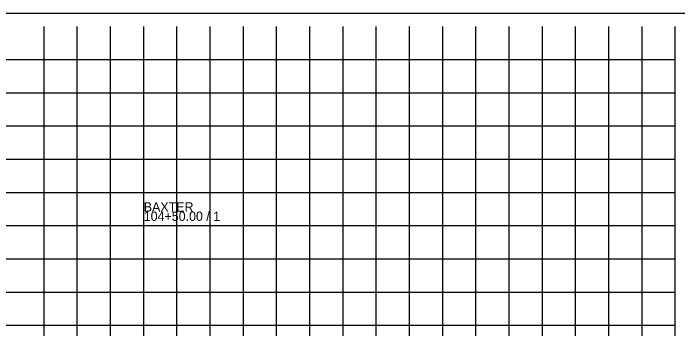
# Model space of a CAD drawing. Extents: x 5868 to 6683, y 2883 to 19120.
# Drawn here: x 6144.5 to 6344.5, y 7508 to 7603 of the extents above; entities that cross this region are included whole.
import ezdxf

# ---------------------------------------------------------------- set-up
doc = ezdxf.new("R2010")
doc.units = 0
for name, color, linetype in [('DESIGN - SCRATCH - User 1', 7, 'Continuous'), ('DESIGN - SHEET - Light Grid', 7, 'Continuous'), ('DESIGN - SHEET - Linework', 7, 'Continuous'), ('DESIGN - SHEET - Plot Shape', 7, 'Continuous')]:
    doc.layers.add(name, color=color, linetype=linetype)

msp = doc.modelspace()

# ---------------------------------------------------------------- linework, layer by layer
at = {"layer": 'DESIGN - SCRATCH - User 1'}
msp.add_line((6193.78, 7445.07), (6193.78, 7538.06), dxfattribs=at)
at = {"layer": 'DESIGN - SHEET - Light Grid'}
msp.add_line((6193.78, 7445.07), (6193.78, 7543.29), dxfattribs=at)
at = {"layer": 'DESIGN - SHEET - Linework'}
for p, q in [((6153.78, 7389.07), (6153.78, 7599.07)), ((6163.78, 7389.07), (6163.78, 7599.07)), ((6173.78, 7389.07), (6173.78, 7599.07)), ((6183.78, 7389.07), (6183.78, 7599.07)), ((6193.78, 7389.07), (6193.78, 7599.07)), ((6203.78, 7389.07), (6203.78, 7599.07)), ((6213.78, 7389.07), (6213.78, 7599.07)), ((6223.78, 7389.07), (6223.78, 7599.07)), ((6233.78, 7389.07), (6233.78, 7599.07)), ((6243.78, 7389.07), (6243.78, 7599.07)), ((6253.78, 7389.07), (6253.78, 7599.07)), ((6263.78, 7389.07), (6263.78, 7599.07)), ((6273.78, 7389.07), (6273.78, 7599.07)), ((6283.78, 7389.07), (6283.78, 7599.07)), ((6293.78, 7389.07), (6293.78, 7599.07)), ((6303.78, 7389.07), (6303.78, 7599.07)), ((6313.78, 7389.07), (6313.78, 7599.07)), ((6323.78, 7389.07), (6323.78, 7599.07)), ((6333.78, 7389.07), (6333.78, 7599.07)), ((6043.78, 7589.07), (6343.78, 7589.07)), ((6043.78, 7579.07), (6343.78, 7579.07)), ((6043.78, 7569.07), (6343.78, 7569.07)), ((6043.78, 7559.07), (6343.78, 7559.07)), ((6043.78, 7549.07), (6343.78, 7549.07)), ((6043.78, 7539.07), (6343.78, 7539.07)), ((6043.78, 7529.07), (6343.78, 7529.07)), ((6043.78, 7519.07), (6343.78, 7519.07)), ((6043.78, 7509.07), (6343.78, 7509.07))]:
    msp.add_line(p, q, dxfattribs=at)
msp.add_lwpolyline([(6043.78, 7599.07), (6043.78, 7389.07), (6343.78, 7389.07), (6343.78, 7599.07)], dxfattribs=at)
at = {"layer": 'DESIGN - SHEET - Plot Shape'}
msp.add_lwpolyline([(6023.78, 7603.01), (6363.78, 7603.01), (6363.78, 7385.13), (6023.78, 7385.13)], close=True, dxfattribs=at)

# ---------------------------------------------------------------- texts
at = {"layer": 'DESIGN - SHEET - Light Grid'}
for s, p in [('BAXTER', (6183.78, 7543.29)), ('104+50.00 / 1', (6183.78, 7540.49))]:
    msp.add_text(s, height=2.8, dxfattribs=at).set_placement(p)

doc.saveas('drawing.dxf')
